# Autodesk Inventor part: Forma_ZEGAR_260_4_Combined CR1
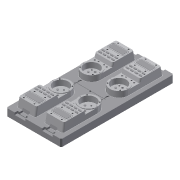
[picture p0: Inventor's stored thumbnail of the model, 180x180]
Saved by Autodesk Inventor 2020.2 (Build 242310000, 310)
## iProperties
Created: 2015-01
Part Number: Forma_ZEGAR_260_4_Combined CR1
Material: Ogólny
Document SubType Name: Modeling
Designer: F.Stasiak
Density: 1 g/cm^3
Appearance: Domyślna
Catalog Web Link: www.expertbooks.pl
Manager: www.cadconsulting.pl
Company: Fabian Stasiak CAD Consulting
Author: F.Stasiak
Subject: Zbiór ćwiczeń. Autodesk Inventor 2020. Kurs Professional
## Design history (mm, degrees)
node "Forma_ZEGAR_260_4_AsmContainer" dims "d0" = 10
sketch "Szkic1"
  geometry: L1 (0, 320)-(156, 320) reference; L2 (156, 320)-(156, 0) reference; L3 (156, 0)-(0, 0) reference; L4 (0, 0)-(0, 320) reference; L5 (0, 320)-(156, 320) reference; L6 (156, 320)-(156, 0) reference; L7 (156, 0)-(0, 0) reference; L8 (0, 0)-(0, 320) reference; L9 (0, 320)-(156, 320) reference; L10 (156, 320)-(156, 0) reference; L11 (156, 0)-(0, 0) reference; L12 (0, 0)-(0, 320) reference; L13 (0, 320)-(156, 320) reference; L14 (156, 320)-(156, 0) reference; L15 (156, 0)-(0, 0) reference; L16 (0, 0)-(0, 320) reference; L17 (156, 320)-(0, 320); L18 (0, 320)-(0, 0); L19 (0, 0)-(156, 0); L20 (156, 0)-(156, 320)
  constraints: 8 end point, 2 parallel, 1 horizontal, 1 perpendicular
sketch "Szkic2"
  geometry: L1 (78, 160)-(-78, 160) reference; L2 (-78, 160)-(-78, -160) reference; L3 (-78, -160)-(78, -160) reference; L4 (78, -160)-(78, 160) reference
sketch "Szkic3"
  geometry: L1 (78, 160)-(-78, 160) reference; L2 (-78, 160)-(-78, -160) reference; L3 (-78, -160)-(78, -160) reference; L4 (78, -160)-(78, 160) reference
sketch "Szkic4"
  geometry: L1 (78, 160)-(-78, 160) reference; L2 (-78, 160)-(-78, -160) reference; L3 (-78, -160)-(78, -160) reference; L4 (78, -160)-(78, 160) reference
sketch "Szkic5"
  geometry: L1 (78, 160)-(-78, 160) reference; L2 (-78, 160)-(-78, -160) reference; L3 (-78, -160)-(78, -160) reference; L4 (78, -160)-(78, 160) reference
chamfer "Faza1" distance "d1" = 3; stored, may be unused: second distance "d2" = 3, angle "d3" = 45 deg
chamfer "Faza2" distance "d4" = 3; stored, may be unused: second distance "d5" = 3, angle "d6" = 45 deg
chamfer "Faza3" distance "d7" = 3; stored, may be unused: second distance "d8" = 3, angle "d9" = 45 deg
chamfer "Faza4" distance "d10" = 3; stored, may be unused: second distance "d11" = 3, angle "d12" = 45 deg
sketch "Szkic6"
  geometry: 1 further point
hole "Otwór1" sketch "Szkic6" at (75, 160) diameter "d13" = 3.5; stored, may be unused: countersink angle "d17" = 90 deg, drill point angle "d19" = 0 deg; dims "d14" = 6, "d15" = 4, "d16" = 2, "d18" = 8
sketch "Szkic7"
  geometry: 1 further point
hole "Otwór2" sketch "Szkic7" at (21, 294) diameter "d20" = 4; stored, may be unused: countersink angle "d24" = 90 deg, drill point angle "d26" = 0 deg; dims "d21" = 6, "d22" = 4, "d23" = 2, "d25" = 8
feature "Rzeźbienie1"
sketch "Szkic8"
  geometry: 1 further point
hole "Otwór3" sketch "Szkic8" at (51, 294) diameter "d27" = 4; stored, may be unused: countersink angle "d31" = 90 deg, drill point angle "d33" = 0 deg; dims "d28" = 6, "d29" = 4, "d30" = 2, "d32" = 8
feature "Rzeźbienie2"
sketch "Szkic9"
  geometry: 1 further point
hole "Otwór4" sketch "Szkic9" at (21, 263.5) diameter "d34" = 4; stored, may be unused: countersink angle "d38" = 90 deg, drill point angle "d40" = 0 deg; dims "d35" = 6, "d36" = 4, "d37" = 2, "d39" = 8
feature "Rzeźbienie3"
sketch "Szkic10"
  geometry: 1 further point
hole "Otwór5" sketch "Szkic10" at (51, 263.5) diameter "d41" = 4; stored, may be unused: countersink angle "d45" = 90 deg, drill point angle "d47" = 0 deg; dims "d42" = 6, "d43" = 4, "d44" = 2, "d46" = 8
feature "Rzeźbienie4"
sketch "Szkic11"
  geometry: 1 further point
hole "Otwór6" sketch "Szkic11" at (28, 231.2) diameter "d48" = 4; stored, may be unused: countersink angle "d52" = 90 deg, drill point angle "d54" = 0 deg; dims "d49" = 6, "d50" = 4, "d51" = 2, "d53" = 8
feature "Rzeźbienie5"
sketch "Szkic12"
  geometry: 1 further point
hole "Otwór7" sketch "Szkic12" at (44, 231.2) diameter "d55" = 4; stored, may be unused: countersink angle "d59" = 90 deg, drill point angle "d61" = 0 deg; dims "d56" = 6, "d57" = 4, "d58" = 2, "d60" = 8
feature "Rzeźbienie6"
sketch "Szkic13"
  geometry: 1 further point
hole "Otwór8" sketch "Szkic13" at (26.5, 214) diameter "d62" = 4; stored, may be unused: countersink angle "d66" = 90 deg, drill point angle "d68" = 0 deg; dims "d63" = 6, "d64" = 4, "d65" = 2, "d67" = 8
feature "Rzeźbienie7"
sketch "Szkic14"
  geometry: 1 further point
hole "Otwór9" sketch "Szkic14" at (45.5, 214) diameter "d69" = 4; stored, may be unused: countersink angle "d73" = 90 deg, drill point angle "d75" = 0 deg; dims "d70" = 6, "d71" = 4, "d72" = 2, "d74" = 8
feature "Rzeźbienie8"
sketch "Szkic15"
  geometry: 1 further point
hole "Otwór10" sketch "Szkic15" at (18, 189) diameter "d76" = 4; stored, may be unused: countersink angle "d80" = 90 deg, drill point angle "d82" = 0 deg; dims "d77" = 6, "d78" = 4, "d79" = 2, "d81" = 8
feature "Rzeźbienie9"
sketch "Szkic16"
  geometry: 1 further point
hole "Otwór11" sketch "Szkic16" at (36, 195) diameter "d83" = 4; stored, may be unused: countersink angle "d87" = 90 deg, drill point angle "d89" = 0 deg; dims "d84" = 6, "d85" = 4, "d86" = 2, "d88" = 8
feature "Rzeźbienie10"
sketch "Szkic17"
  geometry: 1 further point
hole "Otwór12" sketch "Szkic17" at (54, 189) diameter "d90" = 4; stored, may be unused: countersink angle "d94" = 90 deg, drill point angle "d96" = 0 deg; dims "d91" = 6, "d92" = 4, "d93" = 2, "d95" = 8
feature "Rzeźbienie11"
feature "Rzeźbienie12"
node "Bryła1"
node "Forma_ZEGAR_260_4_ZEGAR_260_CR_1:1" dims "d0" = 10
node "Forma_ZEGAR_260_4_ZEGAR_260_CR_2:1" dims "d0" = 10
node "Forma_ZEGAR_260_4_ZEGAR_260_CR_3:1" dims "d0" = 10
node "Forma_ZEGAR_260_4_ZEGAR_260_CR_4:1" dims "d0" = 10
feature "Powierzchnia1"
body "Srf1"
feature "Powierzchnia2"
body "Srf2"
feature "Powierzchnia3"
body "Srf3"
feature "Powierzchnia4"
body "Srf4"
feature "Powierzchnia5"
body "Srf5"
feature "Powierzchnia6"
body "Srf6"
feature "Powierzchnia7"
body "Srf7"
feature "Powierzchnia8"
body "Srf8"
feature "Powierzchnia9"
body "Srf9"
feature "Powierzchnia10"
body "Srf10"
feature "Powierzchnia11"
body "Srf11"
feature "Powierzchnia12"
body "Srf12"
feature "Powierzchnia13"
body "Srf13"
feature "Powierzchnia14"
body "Srf14"
feature "Powierzchnia15"
body "Srf15"
feature "Powierzchnia16"
body "Srf16"
feature "Powierzchnia17"
body "Srf17"
feature "Powierzchnia18"
body "Srf18"
feature "Powierzchnia19"
body "Srf19"
feature "Powierzchnia20"
body "Srf20"
feature "Powierzchnia21"
body "Srf21"
feature "Powierzchnia22"
body "Srf22"
feature "Powierzchnia23"
body "Srf23"
feature "Powierzchnia24"
body "Srf24"
feature "Powierzchnia25"
body "Srf25"
feature "Powierzchnia26"
body "Srf26"
feature "Powierzchnia27"
body "Srf27"
feature "Powierzchnia28"
body "Srf28"
feature "Powierzchnia29"
body "Srf29"
feature "Powierzchnia30"
body "Srf30"
feature "Powierzchnia31"
body "Srf31"
feature "Powierzchnia32"
body "Srf32"
feature "Powierzchnia33"
body "Srf33"
feature "Powierzchnia34"
body "Srf34"
